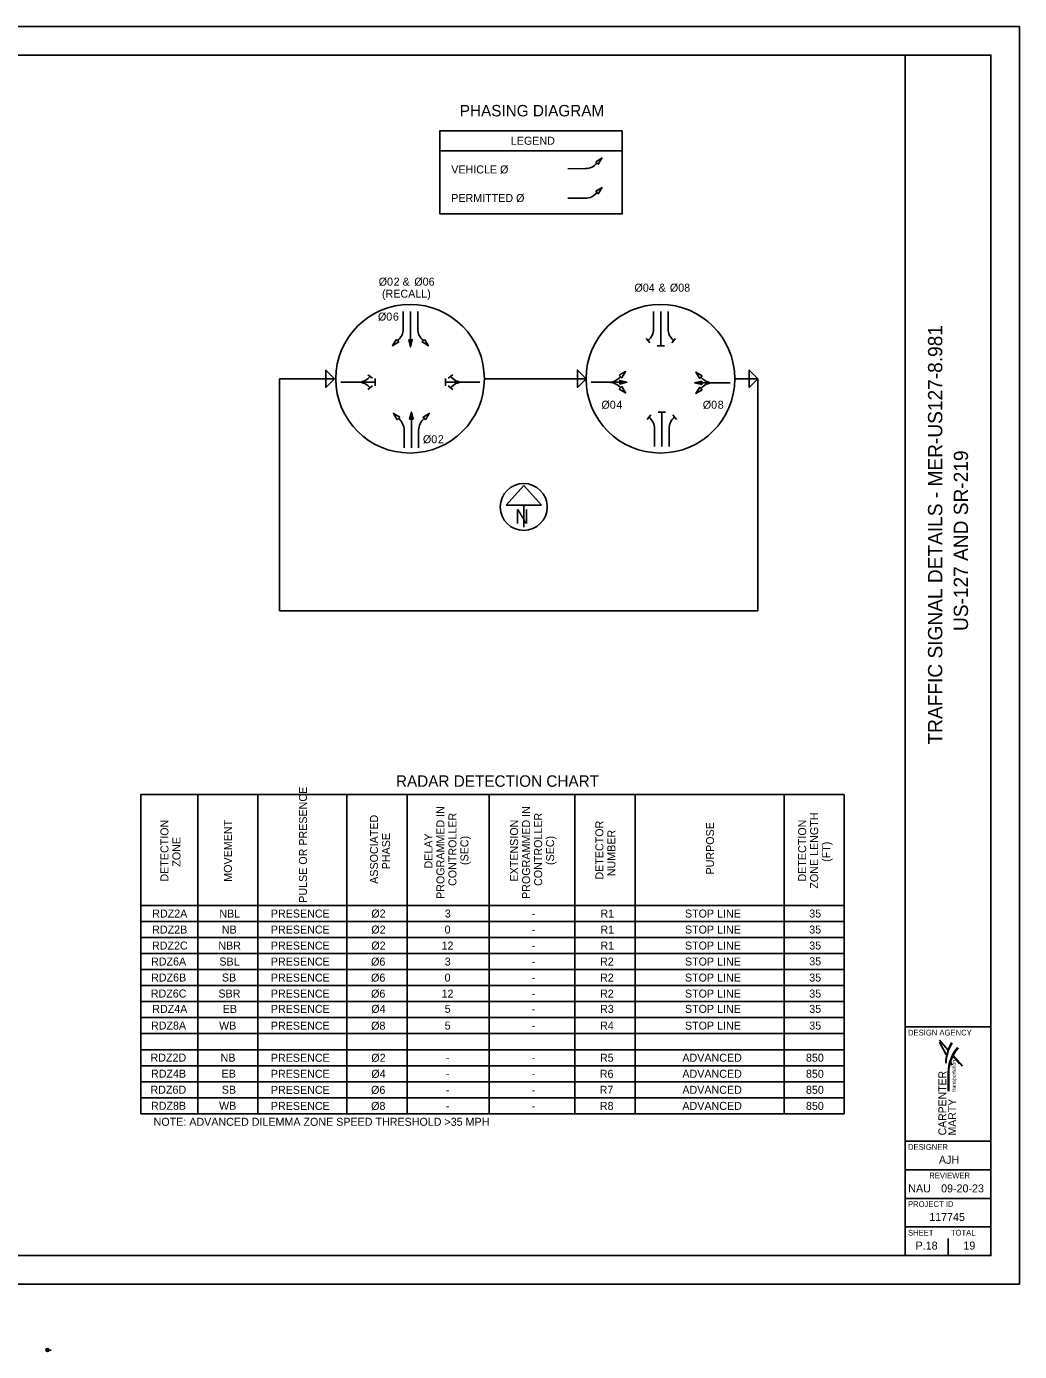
# Model space of a CAD drawing. Extents: x 0 to 696348, y -15235 to 440.
# Drawn here: x 332.7 to 680, y -23.6 to 440 of the extents above; entities that cross this region are included whole.
import ezdxf

# ---------------------------------------------------------------- set-up
doc = ezdxf.new("R2010")
doc.units = 0
for name, color, linetype in [('SC_Scratch1', 7, 'Continuous'), ('SH_Cut_Line', 7, 'Continuous'), ('SH_Data', 7, 'Continuous'), ('SH_Masking', 7, 'Continuous'), ('SH_Text', 7, 'Continuous'), ('UT_X_San_Storm_Line', 7, 'Continuous')]:
    doc.layers.add(name, color=color, linetype=linetype)

msp = doc.modelspace()

# ---------------------------------------------------------------- linework, layer by layer
at = {"layer": 'SC_Scratch1'}
for p, q in [((372.65, 171.26), (618.72, 171.26)), ((372.65, 171.26), (372.65, 59.57)), ((392.56, 171.26), (392.56, 59.57)), ((413.64, 171.26), (413.64, 59.57)), ((444.76, 171.26), (444.76, 59.57)), ((465.84, 171.26), (465.84, 59.57)), ((494.53, 171.26), (494.53, 59.57)), ((524.51, 171.26), (524.51, 59.57)), ((545.59, 171.26), (545.59, 59.57)), ((597.64, 171.26), (597.64, 59.57)), ((618.72, 171.26), (618.72, 59.57)), ((372.65, 132.48), (618.72, 132.48)), ((372.65, 126.88), (618.72, 126.88)), ((372.65, 121.28), (618.72, 121.28)), ((372.65, 115.68), (618.72, 115.68)), ((372.65, 110.08), (618.72, 110.08)), ((372.65, 110.08), (618.72, 110.08)), ((372.65, 104.48), (618.72, 104.48)), ((372.65, 98.88), (618.72, 98.88)), ((372.65, 93.26), (618.72, 93.26)), ((372.65, 87.65), (618.72, 87.65)), ((372.65, 82.03), (618.72, 82.03)), ((372.65, 82.03), (618.72, 82.03)), ((372.65, 76.42), (618.72, 76.42)), ((372.65, 76.42), (618.72, 76.42)), ((372.65, 70.8), (618.72, 70.8)), ((372.65, 70.8), (618.72, 70.8)), ((372.65, 65.19), (618.72, 65.19)), ((372.65, 65.19), (618.72, 65.19)), ((372.65, 59.57), (618.72, 59.57))]:
    msp.add_line(p, q, dxfattribs=at)
at = {"layer": 'SH_Cut_Line'}
msp.add_circle((506.6, 271.91), 8.2, dxfattribs=at)
at = {"layer": 'SH_Data'}
msp.add_lwpolyline([(0, 0), (680, 0), (680, 440), (0, 440)], close=True, dxfattribs=at)
at = {"layer": 'SH_Masking'}
for p, q in [((506.6, 279.38), (500.45, 272.56)), ((512.76, 272.56), (506.6, 279.38)), ((500.45, 272.56), (512.76, 272.56)), ((506.6, 272.56), (506.6, 264.82)), ((654.41, 80.33), (652.03, 84.64)), ((659.03, 77.05), (656.68, 79.83)), ((656.78, 80.03), (660.12, 76.32)), ((656.22, 76.81), (655.79, 77.6)), ((656.4, 76.67), (655.83, 77.72)), ((655.1, 67.55), (655.1, 74.08)), ((655.23, 67.55), (655.23, 74.08)), ((339.47, -23.04), (340.52, -23.04)), ((340, -23.04), (341.35, -23.04))]:
    msp.add_line(p, q, dxfattribs=at)
for points in [[(654.92, 82.09), (652.02, 85.32)], [(652.02, 85.32), (654.88, 81.96)], [(654.41, 80.33), (652.03, 84.64)], [(652.03, 84.63), (654.39, 80.22)]]:
    msp.add_lwpolyline(points, dxfattribs=at)
for centre, radius in [((506.6, 271.91), 8.2), ((340, -23.04), 0.521)]:
    msp.add_circle(centre, radius, dxfattribs=at)
for centre, radius, start, end in [((668.65, 77.2), 14.41, 149.5704, 179.5529), ((667.46, 77.23), 13.09, 147.1423, 179.6525), ((668.51, 74.08), 13.41, 139.2898, 180.0106), ((668.67, 73.76), 13.43, 138.5126, 178.6075)]:
    msp.add_arc(centre, radius, start, end, dxfattribs=at)
at = {"layer": 'SH_Text'}
for p, q in [((477.29, 396.53), (541.06, 396.53)), ((521.97, 390.26), (528.08, 390.27)), ((521.97, 379.93), (528.08, 379.93)), ((464.44, 340.34), (464.43, 334.23)), ((464.44, 340.34), (464.43, 334.23)), ((466.97, 327.88), (466.97, 340.34)), ((466.97, 327.88), (466.97, 340.34)), ((469.51, 340.34), (469.51, 334.23)), ((552.02, 340.34), (552.02, 334.23)), ((552.02, 340.34), (552.02, 334.23)), ((554.56, 340.34), (554.56, 328.33)), ((554.56, 340.34), (554.56, 328.33)), ((557.09, 340.34), (557.09, 334.23)), ((557.09, 340.34), (557.09, 334.23)), ((557.09, 340.34), (557.09, 334.23)), ((557.09, 340.34), (557.09, 334.23)), ((550.68, 329.3), (549.4, 330.9)), ((550.68, 329.3), (549.4, 330.9)), ((558.43, 329.3), (559.71, 330.9)), ((558.43, 329.3), (559.71, 330.9)), ((558.43, 329.3), (559.71, 330.9)), ((558.43, 329.3), (559.71, 330.9)), ((555.83, 328.33), (553.29, 328.33)), ((555.83, 328.33), (553.29, 328.33)), ((440.42, 316.76), (421.21, 316.76)), ((421.21, 235.53), (421.21, 316.76)), ((442.61, 315.57), (454.63, 315.57)), ((442.61, 315.57), (448.72, 315.57)), ((442.61, 315.57), (448.72, 315.57)), ((453.65, 316.91), (452.06, 318.19)), ((454.63, 316.84), (454.63, 314.3)), ((479.24, 314.3), (479.24, 316.84)), ((491.25, 315.57), (479.24, 315.57)), ((480.21, 316.91), (481.81, 318.19)), ((491.25, 315.57), (485.14, 315.57)), ((491.25, 315.57), (485.14, 315.57)), ((528.42, 316.76), (492.82, 316.76)), ((530.2, 315.54), (536.31, 315.54)), ((542.66, 315.54), (530.2, 315.54)), ((530.2, 315.54), (536.31, 315.54)), ((566.37, 315.33), (578.83, 315.33)), ((566.37, 315.33), (578.83, 315.33)), ((578.83, 315.33), (572.72, 315.33)), ((578.83, 315.33), (572.72, 315.33)), ((580.4, 316.76), (588.53, 316.76)), ((588.53, 316.76), (588.53, 235.53)), ((453.65, 314.23), (452.06, 312.95)), ((480.21, 314.23), (481.81, 312.95)), ((467.29, 305.09), (467.29, 292.63)), ((551, 304.12), (549.72, 302.52)), ((551, 304.12), (549.72, 302.52)), ((553.61, 305.09), (556.14, 305.09)), ((554.88, 293.08), (554.88, 305.09)), ((558.75, 304.12), (560.03, 302.52)), ((464.75, 292.63), (464.75, 298.74)), ((469.83, 292.63), (469.83, 298.74)), ((552.34, 293.08), (552.34, 299.19)), ((552.34, 293.08), (552.34, 299.19)), ((557.41, 293.08), (557.41, 299.19)), ((588.53, 235.53), (421.21, 235.53)), ((655, 70), (655, 70)), ((655, 10), (655, 16)), ((647.5, 13.5), (647.5, 13.5))]:
    msp.add_line(p, q, dxfattribs=at)
for points in [[(541.06, 403.53), (477.29, 403.53), (477.29, 374.44), (541.06, 374.44)], [(531.77, 392.69), (533.98, 394.01), (532.65, 391.8)], [(531.77, 382.35), (533.98, 383.67), (532.65, 381.46)], [(462.01, 330.54), (460.69, 328.33), (462.9, 329.66)], [(462.01, 330.54), (460.69, 328.33), (462.9, 329.66)], [(466.35, 330.38), (466.97, 327.88), (467.6, 330.38)], [(466.35, 330.38), (466.97, 327.88), (467.6, 330.38)], [(471.93, 330.54), (473.25, 328.33), (471.04, 329.66)], [(440.42, 316.76), (437.39, 319.79), (437.38, 313.73)], [(528.42, 316.76), (525.39, 319.79), (525.39, 313.73)], [(540, 317.97), (542.21, 319.29), (540.88, 317.08)], [(540.16, 314.92), (542.66, 315.54), (540.16, 316.17)], [(568.87, 315.96), (566.37, 315.33), (568.87, 314.71)], [(568.87, 315.96), (566.37, 315.33), (568.87, 314.71)], [(569.03, 317.76), (566.81, 319.08), (568.14, 316.87)], [(588.53, 316.76), (585.5, 319.79), (585.49, 313.73)], [(540, 313.12), (542.21, 311.8), (540.88, 314.01)], [(569.03, 312.91), (566.81, 311.59), (568.14, 313.79)], [(462.33, 302.43), (461.01, 304.64), (463.21, 303.32)], [(467.91, 302.59), (467.29, 305.09), (466.66, 302.59)], [(472.25, 302.43), (473.57, 304.64), (471.36, 303.32)]]:
    msp.add_lwpolyline(points, close=True, dxfattribs=at)
for centre in [(466.83, 316.76), (554.41, 316.76)]:
    msp.add_circle(centre, 25.99, dxfattribs=at)
for centre, start, end in [((528.08, 395.57), 270.0129, 321.2136), ((528.08, 385.23), 270, 321.2007), ((459.13, 334.23), 308.7864, 359.9871), ((459.13, 334.23), 308.7864, 359.9871), ((474.81, 334.23), 180, 231.2007), ((546.72, 334.23), 308.7993, 0), ((546.72, 334.23), 308.7993, 0), ((562.39, 334.23), 180, 231.2007), ((562.39, 334.23), 180, 231.2007), ((562.39, 334.23), 180, 231.2007), ((562.39, 334.23), 180, 231.2007), ((448.72, 320.87), 270, 321.2007), ((448.72, 310.27), 38.7993, 90), ((485.14, 320.87), 218.7993, 270), ((485.14, 310.27), 90, 141.2007), ((536.31, 320.85), 270, 321.2007), ((536.31, 310.24), 38.7864, 89.9871), ((572.72, 320.63), 218.7864, 269.9871), ((572.72, 310.03), 90, 141.2007), ((459.45, 298.74), 360, 51.2007), ((475.13, 298.74), 128.7864, 179.9871), ((547.04, 299.19), 360, 51.2007), ((547.04, 299.19), 360, 51.2007), ((562.71, 299.19), 128.7993, 180)]:
    msp.add_arc(centre, 5.3, start, end, dxfattribs=at)
at = {"layer": 'UT_X_San_Storm_Line'}
for p, q in [((640, 10), (640, 430)), ((640, 90), (670, 90)), ((640, 50), (670, 50)), ((640, 40), (670, 40)), ((640, 30), (670, 30)), ((640, 20), (670, 20))]:
    msp.add_line(p, q, dxfattribs=at)
msp.add_lwpolyline([(30, 430), (670, 430), (670, 10), (30, 10)], close=True, dxfattribs=at)

# ---------------------------------------------------------------- texts
at = {"layer": 'SC_Scratch1'}
for s, p in [('PULSE OR PRESENCE', (430.78, 133.43)), ('PROGRAMMED IN', (478.85, 134.78)), ('PROGRAMMED IN', (508.82, 134.78)), ('MOVEMENT', (404.52, 140.79)), ('ASSOCIATED', (455.61, 140.06)), ('CONTROLLER', (483.05, 139.31)), ('CONTROLLER', (513.02, 139.31)), ('ZONE LENGTH', (609.58, 138.38)), ('DETECTION', (382.32, 140.84)), ('PHASE', (459.81, 145.14)), ('EXTENSION', (504.62, 140.87)), ('DETECTOR', (534.45, 141.54)), ('NUMBER', (538.65, 142.72)), ('PURPOSE', (573.16, 143.32)), ('DETECTION ', (605.38, 140.88)), ('ZONE', (386.52, 146.05)), ('DELAY ', (474.65, 145.41)), ('(SEC)', (487.25, 146.64)), ('(SEC)', (517.22, 146.64)), ('(FT)', (613.78, 147.74))]:
    msp.add_text(s, height=2.8, rotation=90, dxfattribs=at).set_placement(p)
for s, p in [('RDZ2A', (376.65, 128.26)), ('NBL', (400.12, 128.26)), ('PRESENCE', (418.14, 128.26)), ('Ø2', (453.28, 128.26)), ('3', (478.98, 128.26)), ('R1', (533.41, 128.26)), ('STOP LINE', (562.98, 128.26)), ('35', (606.46, 128.26)), ('RDZ2B', (376.63, 122.66)), ('NB', (401.01, 122.66)), ('PRESENCE', (418.14, 122.66)), ('Ø2', (453.28, 122.66)), ('0', (478.9, 122.66)), ('-', (509.38, 128.26)), ('R1', (533.41, 122.66)), ('STOP LINE', (562.98, 122.66)), ('35', (606.46, 122.66)), ('-', (509.38, 122.66)), ('RDZ2C', (376.56, 117.06)), ('NBR', (399.77, 117.06)), ('PRESENCE', (418.14, 117.06)), ('Ø2', (453.28, 117.06)), ('12', (477.85, 117.06)), ('-', (509.38, 117.06)), ('R1', (533.41, 117.06)), ('STOP LINE', (562.98, 117.06)), ('35', (606.46, 117.06)), ('RDZ6A', (376.24, 111.48)), ('SBL', (400.13, 111.48)), ('PRESENCE', (418.14, 111.45)), ('Ø6', (453.2, 111.45)), ('3', (478.98, 111.46)), ('-', (509.38, 111.46)), ('R2', (533.28, 111.46)), ('STOP LINE', (562.98, 111.46)), ('35', (606.46, 111.55)), ('RDZ6B', (376.25, 105.88)), ('SB', (401.02, 105.88)), ('PRESENCE', (418.14, 105.85)), ('Ø6', (453.2, 105.85)), ('0', (478.9, 105.86)), ('-', (509.38, 105.86)), ('R2', (533.28, 105.86)), ('STOP LINE ', (562.98, 105.86)), ('35', (606.46, 105.86)), ('RDZ6C', (376.15, 100.28)), ('SBR', (399.81, 100.28)), ('PRESENCE', (418.14, 100.25)), ('Ø6', (453.2, 100.25)), ('12', (477.85, 100.26)), ('R2', (533.28, 100.26)), ('STOP LINE', (562.98, 100.26)), ('35', (606.46, 100.26)), ('RDZ4A', (376.65, 94.91)), ('EB', (401.33, 94.91)), ('PRESENCE', (418.14, 94.91)), ('Ø4', (453.28, 94.91)), ('5', (478.95, 94.91)), ('-', (509.38, 100.26)), ('R3', (533.29, 94.91)), ('STOP LINE', (562.98, 94.91)), ('35', (606.46, 94.91)), ('-', (509.38, 94.91)), ('RDZ8A', (376.21, 89.08)), ('WB', (400.02, 89.08)), ('PRESENCE', (418.14, 89.03)), ('Ø8', (453.22, 89.03)), ('5', (478.95, 89.05)), ('-', (509.38, 89.05)), ('R4', (533.29, 89.05)), ('STOP LINE', (562.98, 89.05)), ('35', (606.46, 89.05)), ('RDZ2D', (376.04, 77.86)), ('NB', (400.57, 77.86)), ('PRESENCE', (418.14, 77.8)), ('Ø2', (453.28, 77.8)), ('-', (479.4, 77.82)), ('-', (509.38, 77.82)), ('R5', (533.26, 77.82)), ('ADVANCED', (562.08, 77.82)), ('850', (605.31, 77.82)), ('RDZ4B', (376.22, 72.25)), ('EB', (400.91, 72.25)), ('PRESENCE', (418.14, 72.19)), ('Ø4', (453.28, 72.19)), ('R6', (533.2, 72.2)), ('ADVANCED', (562.08, 72.2)), ('850', (605.31, 72.2)), ('-', (479.4, 72.2)), ('-', (509.38, 72.2)), ('RDZ6D', (376.04, 66.63)), ('SB', (400.99, 66.63)), ('PRESENCE', (418.14, 66.57)), ('Ø6', (453.2, 66.57)), ('-', (479.4, 66.59)), ('-', (509.38, 66.59)), ('R7', (533.14, 66.59)), ('ADVANCED', (562.08, 66.59)), ('850', (605.31, 66.59)), ('RDZ8B', (376.22, 61.02)), ('WB', (400.02, 61.02)), ('PRESENCE', (418.14, 60.96)), ('Ø8', (453.22, 60.96)), ('-', (479.4, 60.97)), ('-', (509.38, 60.97)), ('R8', (533.22, 60.97)), ('ADVANCED', (562.08, 60.97)), ('850', (605.31, 60.97)), ('NOTE: ADVANCED DILEMMA ZONE SPEED THRESHOLD >35 MPH', (377.13, 55.4))]:
    msp.add_text(s, height=2.8, dxfattribs=at).set_placement(p)
at = {"layer": 'SH_Masking'}
for s, height, p in [('PHASING DIAGRAM', 4, (484.23, 408.55)), ('LEGEND', 2.8, (502.09, 398.63)), ('VEHICLE Ø', 2.8, (481.25, 388.59)), ('PERMITTED Ø', 2.8, (481.25, 378.59)), ('Ø0', 2.8, (455.87, 349.33)), ('(RECALL)', 2.8, (457.02, 345.13)), ('2 & ', 2.8, (461.09, 349.33)), ('Ø06', 2.8, (468.33, 349.33)), ('Ø04', 2.8, (545.33, 347.23)), (' & ', 2.8, (552.72, 347.23)), ('Ø08', 2.8, (557.72, 347.23)), ('Ø0', 2.8, (455.61, 337.11)), ('6', 2.8, (460.83, 337.11)), ('Ø0', 2.8, (533.77, 306.27)), ('4', 2.8, (538.99, 306.27)), ('Ø0', 2.8, (569.23, 306.27)), ('8', 2.8, (574.45, 306.27)), ('Ø0', 2.8, (471.34, 294.19)), ('2', 2.8, (476.55, 294.19)), ('RADAR DETECTION CHART', 4, (461.9, 174.01)), ('2', 0.0656, (339.97, -22.91)), ('Drawing - Copy-1', 0.0656, (340.65, -22.91)), ('1:1', 0.0656, (340.65, -23.24))]:
    msp.add_text(s, height=height, dxfattribs=at).set_placement(p)
for s, height, rotation, p in [('N', 5, 360, (503.58, 266.08)), ('CARPENTER ', 2.735, 90, (654.38, 52.04)), ('transportation', 1.3298, 90, (657.7, 67.28)), ('MARTY', 2.735, 90, (657.81, 52.04))]:
    msp.add_text(s, height=height, rotation=rotation, dxfattribs=at).set_placement(p)
at = {"layer": 'SH_Text'}
for s, p in [('TRAFFIC SIGNAL DETAILS - MER-US127-8.981', (653, 188.79)), ('US-127 AND SR-219', (662, 228.5))]:
    msp.add_text(s, height=5, rotation=90, dxfattribs=at).set_placement(p)
for s, height, p in [('DESIGN AGENCY', 2, (641, 87)), ('DESIGNER', 2, (641, 47)), ('AJH', 2.8, (651.81, 42.1)), ('REVIEWER', 2, (648.44, 37)), ('NAU', 2.8, (641.1, 32.1)), ('09-20-23', 2.8, (652.58, 32.1)), ('PROJECT ID', 2, (641, 27)), ('117745', 2.8, (648.42, 22.1)), ('SHEET', 2, (641, 17)), ('TOTAL', 2, (656, 17)), ('P.18', 2.8, (643.66, 12.1)), ('19', 2.8, (660.38, 12.1))]:
    msp.add_text(s, height=height, dxfattribs=at).set_placement(p)

doc.saveas('drawing.dxf')
